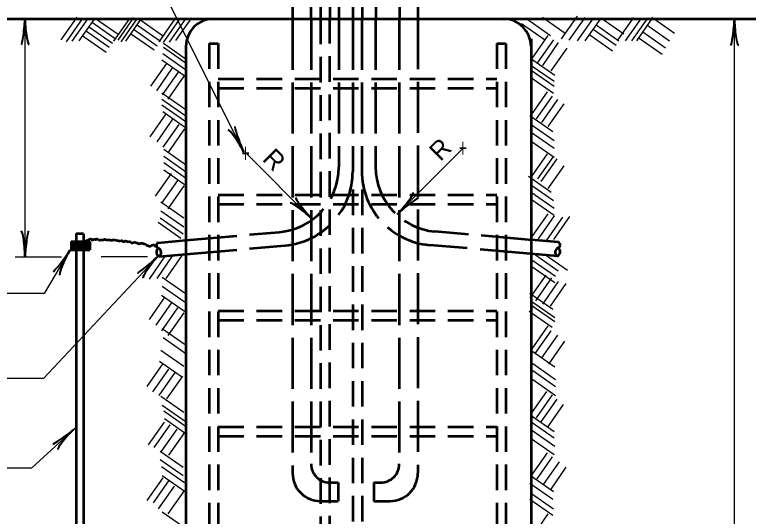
# Model space of a CAD drawing. Extents: x -711 to 145, y 25 to 569.
# Drawn here: x -347.5 to -252.6, y 105.2 to 170 of the extents above; entities that cross this region are included whole.
import ezdxf

# ---------------------------------------------------------------- set-up
doc = ezdxf.new("R2010")
doc.units = 0
doc.header["$LTSCALE"] = 1.1
doc.linetypes.add('LONG_DASHED', pattern=[7.5, 6, -1.5])
doc.linetypes.add('MEDIUM_DASHED', pattern=[4.5, 3, -1.5])
doc.layers.add('1', color=7, linetype='Continuous', lineweight=53)

msp = doc.modelspace()

# ---------------------------------------------------------------- linework, layer by layer
at = {"layer": '1', "lineweight": 25}
for p, q in [((-317.853, 152.275), (-331.719, 180.005)), ((-276.746, 166.889), (-274.682, 169.838)), ((-346.116, 138.621), (-346.116, 169.596)), ((-341.429, 166.753), (-339.365, 169.702)), ((-340.754, 166.528), (-338.689, 169.477)), ((-340.034, 166.573), (-337.969, 169.522)), ((-339.134, 166.618), (-337.069, 169.567)), ((-337.411, 169.003), (-334.462, 166.938)), ((-337.006, 169.543), (-334.057, 167.478)), ((-334.632, 166.573), (-332.568, 169.522)), ((-334.092, 166.708), (-332.028, 169.657)), ((-333.687, 166.528), (-331.622, 169.477)), ((-333.102, 166.573), (-331.037, 169.522)), ((-331.155, 169.318), (-328.206, 167.253)), ((-328.781, 166.528), (-326.716, 169.477)), ((-328.196, 166.438), (-326.131, 169.387)), ((-327.43, 166.483), (-325.366, 169.432)), ((-326.62, 166.663), (-324.555, 169.612)), ((-281.101, 169.408), (-278.152, 167.343)), ((-279.21, 169.678), (-276.261, 167.613)), ((-275.756, 166.709), (-273.691, 169.657)), ((-274.676, 166.619), (-272.611, 169.567)), ((-273.686, 166.619), (-271.621, 169.567)), ((-271.648, 169.588), (-268.699, 167.523)), ((-269.454, 166.709), (-267.39, 169.657)), ((-268.464, 166.619), (-266.399, 169.567)), ((-267.654, 166.619), (-265.589, 169.567)), ((-267.024, 166.619), (-264.959, 169.567)), ((-265.076, 169.678), (-262.127, 167.613)), ((-254.382, 81.637), (-254.382, 169.492)), ((-337.772, 168.418), (-334.822, 166.353)), ((-331.965, 168.058), (-329.016, 165.993)), ((-331.56, 168.643), (-328.611, 166.578)), ((-281.911, 168.868), (-278.962, 166.803)), ((-272.639, 168.148), (-269.69, 166.083)), ((-272.278, 168.688), (-269.329, 166.623)), ((-265.707, 168.688), (-262.758, 166.623)), ((-338.582, 167.247), (-335.633, 165.183)), ((-338.177, 167.877), (-335.228, 165.813)), ((-332.37, 167.517), (-329.421, 165.453)), ((-280.528, 164.368), (-278.463, 167.317)), ((-273.089, 167.427), (-270.14, 165.363)), ((-266.697, 166.977), (-263.748, 164.912)), ((-266.247, 167.787), (-263.298, 165.723)), ((-328.229, 166.347), (-325.28, 164.282)), ((-279.807, 163.828), (-277.743, 166.777)), ((-279.177, 163.468), (-277.112, 166.417)), ((-328.229, 165.807), (-325.28, 163.742)), ((-278.097, 162.748), (-276.032, 165.696)), ((-328.409, 164.186), (-325.46, 162.122)), ((-328.319, 164.997), (-325.37, 162.932)), ((-280.561, 164.276), (-277.612, 162.212)), ((-329.861, 160.767), (-327.796, 163.716)), ((-280.651, 163.466), (-277.702, 161.401)), ((-329.096, 160.182), (-327.031, 163.131)), ((-328.331, 159.641), (-326.266, 162.59)), ((-280.651, 162.836), (-277.702, 160.771)), ((-327.611, 159.101), (-325.546, 162.05)), ((-280.741, 161.936), (-277.792, 159.871)), ((-328.409, 159.91), (-325.46, 157.846)), ((-280.618, 157.076), (-278.553, 160.025)), ((-279.987, 156.536), (-277.923, 159.485)), ((-328.409, 159.1), (-325.46, 157.035)), ((-279.267, 156.085), (-277.202, 159.034)), ((-278.457, 155.545), (-276.392, 158.494)), ((-328.409, 158.38), (-325.46, 156.315)), ((-329.951, 154.24), (-327.886, 157.189)), ((-328.319, 157.48), (-325.37, 155.415)), ((-280.831, 156.984), (-277.882, 154.92)), ((-329.051, 153.565), (-326.986, 156.514)), ((-328.241, 152.889), (-326.176, 155.838)), ((-280.651, 155.814), (-277.702, 153.749)), ((-327.521, 152.304), (-325.456, 155.253)), ((-280.651, 154.824), (-277.702, 152.759)), ((-280.651, 153.654), (-277.702, 151.589)), ((-328.184, 152.618), (-325.235, 150.554)), ((-280.618, 149.064), (-278.553, 152.013)), ((-328.184, 151.718), (-325.235, 149.653)), ((-328.184, 150.908), (-325.235, 148.843)), ((-279.807, 148.793), (-277.743, 151.742)), ((-279.357, 148.433), (-277.292, 151.382)), ((-328.184, 149.963), (-325.235, 147.898)), ((-278.457, 147.533), (-276.392, 150.482)), ((-329.231, 146.543), (-327.166, 149.492)), ((-281.011, 149.152), (-278.062, 147.088)), ((-328.421, 145.643), (-326.356, 148.591)), ((-280.741, 148.072), (-277.792, 146.007)), ((-327.611, 144.922), (-325.546, 147.871)), ((-280.651, 147.082), (-277.702, 145.017)), ((-280.651, 146.181), (-277.702, 144.117)), ((-328.544, 145.821), (-325.595, 143.757)), ((-328.544, 144.651), (-325.595, 142.586)), ((-280.528, 141.322), (-278.463, 144.27)), ((-328.634, 143.751), (-325.685, 141.686)), ((-279.717, 141.051), (-277.653, 144)), ((-278.637, 140.871), (-276.572, 143.82)), ((-277.737, 140.961), (-275.672, 143.91)), ((-328.904, 143.211), (-325.955, 141.146)), ((-347.382, 138.703), (-341.382, 138.703)), ((-336.264, 138.748), (-330.264, 138.748)), ((-330.041, 135.83), (-327.976, 138.779)), ((-329.051, 135.92), (-326.986, 138.869)), ((-327.881, 135.92), (-325.816, 138.869)), ((-280.111, 138.979), (-277.161, 136.915)), ((-278.94, 139.07), (-275.991, 137.005)), ((-280.471, 138.259), (-277.522, 136.194)), ((-280.561, 137.449), (-277.612, 135.384)), ((-328.364, 136.099), (-325.415, 134.034)), ((-280.798, 133.399), (-278.733, 136.348)), ((-280.077, 133.039), (-278.013, 135.988)), ((-328.364, 134.928), (-325.415, 132.864)), ((-279.177, 132.589), (-277.112, 135.538)), ((-278.187, 132.319), (-276.122, 135.268)), ((-280.831, 134.028), (-277.882, 131.963)), ((-330.041, 130.608), (-327.976, 133.557)), ((-329.141, 129.888), (-327.076, 132.837)), ((-328.454, 133.758), (-325.505, 131.693)), ((-280.561, 132.948), (-277.612, 130.883)), ((-328.421, 129.168), (-326.356, 132.117)), ((-280.561, 132.408), (-277.612, 130.343)), ((-327.611, 128.538), (-325.546, 131.487)), ((-280.921, 131.687), (-277.972, 129.623)), ((-328.364, 129.437), (-325.415, 127.372)), ((-280.528, 126.828), (-278.463, 129.776)), ((-280.167, 126.197), (-278.103, 129.146)), ((-328.274, 128.267), (-325.325, 126.202)), ((-279.267, 125.657), (-277.202, 128.606)), ((-278.367, 124.847), (-276.302, 127.796)), ((-328.544, 126.646), (-325.595, 124.581)), ((-280.561, 126.556), (-277.612, 124.491)), ((-330.311, 121.966), (-328.247, 124.915)), ((-328.724, 125.206), (-325.775, 123.141)), ((-280.471, 124.936), (-277.522, 122.871)), ((-329.591, 121.246), (-327.526, 124.195)), ((-328.781, 120.796), (-326.716, 123.745)), ((-280.471, 124.035), (-277.522, 121.971)), ((-327.791, 120.346), (-325.726, 123.294)), ((-280.471, 122.865), (-277.522, 120.8)), ((-328.544, 120.705), (-325.595, 118.64)), ((-280.708, 118.365), (-278.643, 121.314)), ((-279.987, 117.915), (-277.923, 120.864)), ((-279.357, 117.375), (-277.292, 120.324)), ((-278.547, 116.655), (-276.482, 119.604)), ((-328.364, 119.534), (-325.415, 117.469)), ((-328.184, 118.814), (-325.235, 116.749)), ((-328.094, 117.824), (-325.145, 115.759)), ((-280.651, 118.184), (-277.702, 116.119)), ((-330.131, 114.404), (-328.067, 117.353)), ((-329.411, 114.044), (-327.346, 116.993)), ((-280.651, 117.374), (-277.702, 115.309)), ((-328.511, 113.504), (-326.446, 116.453)), ((-327.521, 113.053), (-325.456, 116.002)), ((-280.561, 116.293), (-277.612, 114.228)), ((-280.651, 115.213), (-277.702, 113.148)), ((-328.634, 113.592), (-325.685, 111.528)), ((-280.618, 110.443), (-278.553, 113.392)), ((-328.634, 112.512), (-325.685, 110.447)), ((-279.987, 109.903), (-277.923, 112.852)), ((-279.087, 109.273), (-277.022, 112.222)), ((-328.454, 111.612), (-325.505, 109.547)), ((-278.187, 108.552), (-276.122, 111.501)), ((-330.311, 107.202), (-328.247, 110.151)), ((-328.364, 110.442), (-325.415, 108.377)), ((-280.741, 110.442), (-277.792, 108.377)), ((-329.501, 106.932), (-327.436, 109.881)), ((-280.831, 109.451), (-277.882, 107.386)), ((-328.871, 106.122), (-326.806, 109.071)), ((-327.611, 105.491), (-325.546, 108.44)), ((-280.741, 108.191), (-277.792, 106.126)), ((-280.831, 107.381), (-277.882, 105.316)), ((-328.364, 105.76), (-325.415, 103.696)), ((-280.528, 102.521), (-278.463, 105.47))]:
    msp.add_line(p, q, dxfattribs=at)
at = {"layer": '1'}
for p, q in [((-305.538, 177.881), (-305.538, 169.481)), ((-303.738, 177.881), (-303.738, 169.481)), ((-302.538, 177.881), (-302.538, 169.481)), ((-300.738, 177.881), (-300.738, 169.481)), ((-311.546, 176.743), (-311.546, 169.492)), ((-309.146, 176.743), (-309.146, 169.492)), ((-297.708, 176.743), (-297.708, 169.543)), ((-295.308, 176.743), (-295.308, 169.543)), ((-307.923, 174.46), (-307.923, 169.492)), ((-306.723, 174.46), (-306.723, 169.492)), ((-359.367, 169.492), (-318.435, 169.492)), ((-321.725, 169.492), (-253.351, 169.492)), ((-263.611, 169.492), (-244.167, 169.492)), ((-280.687, 166.888), (-280.687, 81.935)), ((-339.509, 141.727), (-338.548, 141.727)), ((-339.509, 141.727), (-339.509, 140.802)), ((-338.548, 141.704), (-338.548, 141.315)), ((-338.548, 141.704), (-338.548, 140.802)), ((-340.139, 140.7), (-337.739, 140.7)), ((-340.139, 140.7), (-340.139, 139.62)), ((-340.094, 140.7), (-340.094, 139.62)), ((-340.083, 140.7), (-340.083, 139.62)), ((-340.06, 140.7), (-340.06, 139.62)), ((-340.038, 140.7), (-340.038, 139.62)), ((-340.004, 140.7), (-340.004, 139.62)), ((-339.947, 140.7), (-339.947, 139.62)), ((-339.891, 140.7), (-339.891, 139.62)), ((-339.835, 140.7), (-339.835, 139.62)), ((-339.812, 140.7), (-339.812, 139.62)), ((-339.767, 140.7), (-339.767, 139.62)), ((-339.756, 140.7), (-339.756, 139.62)), ((-339.722, 140.7), (-339.722, 139.62)), ((-339.689, 140.7), (-339.689, 139.62)), ((-339.689, 140.7), (-339.689, 139.62)), ((-339.677, 140.7), (-339.677, 139.62)), ((-339.666, 140.7), (-339.666, 139.62)), ((-339.632, 140.7), (-339.632, 139.62)), ((-339.61, 140.7), (-339.61, 139.62)), ((-339.599, 140.7), (-339.599, 139.62)), ((-339.565, 140.7), (-339.565, 139.62)), ((-339.565, 140.7), (-339.565, 139.62)), ((-339.554, 140.7), (-339.554, 139.62)), ((-339.52, 140.7), (-339.52, 139.62)), ((-339.509, 140.843), (-339.509, 138.047)), ((-339.486, 140.7), (-339.486, 139.62)), ((-339.486, 140.7), (-339.486, 139.62)), ((-339.441, 140.7), (-339.441, 139.62)), ((-339.441, 140.7), (-339.441, 139.62)), ((-339.419, 140.7), (-339.419, 139.62)), ((-339.418, 140.7), (-339.418, 140.267)), ((-339.374, 140.7), (-339.374, 139.62)), ((-339.374, 140.7), (-339.374, 139.62)), ((-339.34, 140.7), (-339.34, 139.62)), ((-339.317, 140.7), (-339.317, 139.62)), ((-339.295, 140.7), (-339.295, 139.62)), ((-339.261, 140.7), (-339.261, 139.62)), ((-339.239, 140.7), (-339.239, 139.62)), ((-339.205, 140.7), (-339.205, 139.62)), ((-339.171, 140.7), (-339.171, 139.62)), ((-339.16, 140.7), (-339.16, 139.62)), ((-339.149, 140.7), (-339.149, 139.62)), ((-339.126, 140.7), (-339.126, 139.62)), ((-339.104, 140.7), (-339.104, 139.62)), ((-339.092, 140.7), (-339.092, 139.62)), ((-339.07, 140.7), (-339.07, 139.62)), ((-339.059, 140.7), (-339.059, 139.62)), ((-339.047, 140.7), (-339.047, 139.62)), ((-339.025, 140.7), (-339.025, 139.62)), ((-339.025, 140.7), (-339.025, 139.62)), ((-339.025, 140.7), (-339.025, 139.62)), ((-338.991, 140.7), (-338.991, 139.62)), ((-338.991, 140.7), (-338.991, 139.62)), ((-338.957, 140.7), (-338.957, 139.62)), ((-338.957, 140.7), (-338.957, 139.62)), ((-338.946, 140.7), (-338.946, 139.62)), ((-338.924, 140.7), (-338.924, 139.62)), ((-338.879, 140.7), (-338.879, 139.62)), ((-338.867, 140.7), (-338.867, 139.62)), ((-338.867, 140.7), (-338.867, 139.62)), ((-338.845, 140.7), (-338.845, 139.62)), ((-338.811, 140.7), (-338.811, 139.62)), ((-338.8, 140.7), (-338.8, 139.62)), ((-338.789, 140.7), (-338.789, 139.62)), ((-338.777, 140.7), (-338.777, 139.62)), ((-338.766, 140.7), (-338.766, 139.62)), ((-338.732, 140.7), (-338.732, 139.62)), ((-338.71, 140.7), (-338.71, 139.62)), ((-338.699, 140.7), (-338.699, 139.62)), ((-338.676, 140.7), (-338.676, 139.62)), ((-338.642, 140.7), (-338.642, 139.62)), ((-338.62, 140.7), (-338.62, 139.62)), ((-338.62, 140.7), (-338.62, 139.62)), ((-338.608, 140.7), (-338.608, 139.62)), ((-338.597, 140.7), (-338.597, 139.62)), ((-338.575, 140.7), (-338.575, 139.62)), ((-338.575, 140.7), (-338.575, 139.62)), ((-338.564, 140.7), (-338.564, 139.62)), ((-338.548, 140.854), (-338.548, 138.091)), ((-338.541, 140.7), (-338.541, 139.62)), ((-338.541, 140.7), (-338.541, 139.62)), ((-338.53, 140.7), (-338.53, 139.62)), ((-338.507, 140.7), (-338.507, 139.62)), ((-338.485, 140.7), (-338.485, 139.62)), ((-338.474, 140.7), (-338.474, 139.62)), ((-338.459, 140.699), (-338.459, 140.267)), ((-338.451, 140.7), (-338.451, 139.62)), ((-338.44, 140.7), (-338.44, 139.62)), ((-338.429, 140.7), (-338.429, 139.62)), ((-338.395, 140.7), (-338.395, 139.62)), ((-338.361, 140.7), (-338.361, 139.62)), ((-338.35, 140.7), (-338.35, 139.62)), ((-338.339, 140.7), (-338.339, 139.62)), ((-338.316, 140.7), (-338.316, 139.62)), ((-338.305, 140.7), (-338.305, 139.62)), ((-338.293, 140.7), (-338.293, 139.62)), ((-338.26, 140.7), (-338.26, 139.62)), ((-338.215, 140.7), (-338.215, 139.62)), ((-338.204, 140.7), (-338.204, 139.62)), ((-338.204, 140.7), (-338.204, 139.62)), ((-338.204, 140.7), (-338.204, 139.62)), ((-338.192, 140.7), (-338.192, 139.62)), ((-338.159, 140.7), (-338.159, 139.62)), ((-338.159, 140.7), (-338.159, 139.62)), ((-338.147, 140.7), (-338.147, 139.62)), ((-338.136, 140.7), (-338.136, 139.62)), ((-338.114, 140.7), (-338.114, 139.62)), ((-338.102, 140.7), (-338.102, 139.62)), ((-338.091, 140.7), (-338.091, 139.62)), ((-338.069, 140.7), (-338.069, 139.62)), ((-338.046, 140.7), (-338.046, 139.62)), ((-338.035, 140.7), (-338.035, 139.62)), ((-338.024, 140.7), (-338.024, 139.62)), ((-338.024, 140.7), (-338.024, 139.62)), ((-337.99, 140.7), (-337.99, 139.62)), ((-337.967, 140.7), (-337.967, 139.62)), ((-337.967, 140.7), (-337.967, 139.62)), ((-337.956, 140.7), (-337.956, 139.62)), ((-337.956, 140.7), (-337.956, 139.62)), ((-337.922, 140.7), (-337.922, 139.62)), ((-337.911, 140.7), (-337.911, 139.62)), ((-337.911, 140.7), (-337.911, 139.62)), ((-337.889, 140.7), (-337.889, 139.62)), ((-337.889, 140.7), (-337.889, 139.62)), ((-337.889, 140.7), (-337.889, 139.62)), ((-337.877, 140.7), (-337.877, 139.62)), ((-337.877, 140.7), (-337.877, 139.62)), ((-337.832, 140.7), (-337.832, 139.62)), ((-337.821, 140.7), (-337.821, 139.62)), ((-337.81, 140.7), (-337.81, 139.62)), ((-337.787, 140.7), (-337.787, 139.62)), ((-337.787, 140.7), (-337.787, 139.62)), ((-337.776, 140.7), (-337.776, 139.62)), ((-337.776, 140.7), (-337.776, 139.62)), ((-337.742, 140.7), (-337.742, 139.62)), ((-337.739, 140.7), (-337.739, 139.62)), ((-328.929, 140.543), (-325.343, 140.857)), ((-277.118, 140.588), (-280.704, 140.902)), ((-340.139, 139.62), (-337.739, 139.62)), ((-328.772, 138.75), (-325.326, 139.051)), ((-277.275, 138.795), (-280.693, 139.094)), ((-339.509, 138.321), (-339.509, 69.075)), ((-338.548, 138.321), (-338.548, 69.075))]:
    msp.add_line(p, q, dxfattribs=at)
at = {"layer": '1', "linetype": 'LONG_DASHED'}
for p, q in [((-311.525, 169.498), (-311.525, 110.735)), ((-309.125, 169.498), (-309.125, 111.935)), ((-305.549, 169.498), (-305.549, 150.29)), ((-303.749, 169.498), (-303.749, 149.74)), ((-302.579, 169.498), (-302.579, 149.803)), ((-300.779, 169.498), (-300.779, 150.353)), ((-297.725, 169.498), (-297.725, 111.935)), ((-295.325, 169.588), (-295.325, 110.735)), ((-325.325, 140.863), (-313.217, 141.922)), ((-280.548, 140.886), (-293.111, 141.985)), ((-325.325, 139.056), (-312.513, 140.177)), ((-280.705, 139.093), (-293.816, 140.24)), ((-306.725, 109.535), (-305.639, 109.535)), ((-305.639, 109.535), (-305.639, 107.135)), ((-301.005, 109.535), (-300.125, 109.535)), ((-301.005, 109.535), (-301.005, 107.135)), ((-307.925, 107.135), (-305.639, 107.135)), ((-301.005, 107.135), (-298.925, 107.135))]:
    msp.add_line(p, q, dxfattribs=at)
at = {"layer": '1', "linetype": 'MEDIUM_DASHED'}
for p, q in [((-307.925, 169.498), (-307.925, 81.935)), ((-306.725, 169.588), (-306.725, 81.935)), ((-322.325, 166.298), (-322.325, 81.935)), ((-322.325, 166.298), (-321.125, 166.298)), ((-321.125, 166.298), (-321.125, 81.935)), ((-285.125, 166.298), (-285.125, 81.935)), ((-285.125, 166.298), (-283.925, 166.298)), ((-283.925, 166.298), (-283.925, 81.935)), ((-321.125, 161.735), (-285.125, 161.735)), ((-321.125, 160.535), (-285.125, 160.535)), ((-303.725, 147.399), (-303.725, 81.935)), ((-302.525, 147.399), (-302.525, 81.935)), ((-321.125, 146.735), (-285.125, 146.735)), ((-321.125, 145.535), (-285.125, 145.535)), ((-321.125, 131.735), (-285.125, 131.735)), ((-321.125, 130.535), (-285.125, 130.535)), ((-321.125, 116.735), (-285.125, 116.735)), ((-321.125, 115.535), (-285.125, 115.535))]:
    msp.add_line(p, q, dxfattribs=at)
at = {"layer": '1', "lineweight": 35}
for p, q in [((-309.01, 143.594), (-317.496, 152.079)), ((-297.999, 144.224), (-289.513, 152.71))]:
    msp.add_line(p, q, dxfattribs=at)
at = {"layer": '1'}
msp.add_lwpolyline([(-325.325, 165.892), (-325.325, 81.935), (-280.687, 81.935)], dxfattribs=at)
at = {"layer": '1', "lineweight": 25}
for points in [[(-340.311, 139.561), (-343.642, 133.98), (-349.05, 133.98)], [(-328.878, 138.841), (-343.732, 122.997), (-349.298, 122.997)], [(-339.681, 116.515), (-345.262, 111.384), (-369.712, 111.384)]]:
    msp.add_lwpolyline(points, dxfattribs=at)
at = {"layer": '1'}
for centre, radius, start, end in [((-321.725, 165.892), 3.6, 90, 180), ((-284.287, 165.892), 3.6, 0, 90), ((-328.497, 139.324), 0.636, 124.39884, 244.42408), ((-277.561, 139.369), 0.636, 295.57592, 55.60116)]:
    msp.add_arc(centre, radius, start, end, dxfattribs=at)
at = {"layer": '1', "lineweight": 25}
msp.add_arc((-321.725, 165.892), 3.6, 90, 180, dxfattribs=at)
at = {"layer": '1', "linetype": 'LONG_DASHED'}
for centre, radius, start, end in [((-313.949, 150.29), 8.4, 275.00041, 0), ((-292.379, 150.353), 8.4, 180, 264.9999), ((-313.349, 149.74), 9.6, 275.00013, 0), ((-292.979, 149.803), 9.6, 180, 264.9999), ((-306.725, 111.935), 2.4, 180, 270), ((-300.125, 111.935), 2.4, 270, 0), ((-307.925, 110.735), 3.6, 180, 270), ((-298.925, 110.735), 3.6, 270, 0)]:
    msp.add_arc(centre, radius, start, end, dxfattribs=at)
at = {"layer": '1', "lineweight": 40}
for centre, major_axis, ratio, start_param, end_param in [((-346.37, 168.251), (-0.211, -2.108), 0.07063, 6.282307, 8.559703), ((-345.785, 168.286), (-0.187, 2.143), 0.122415, 0.896353, 3.141593), ((-254.636, 168.148), (-0.211, -2.108), 0.07063, 6.282307, 8.559703), ((-254.051, 168.183), (-0.187, 2.143), 0.122415, 0.896353, 3.141593), ((-318.736, 153.298), (1.126, -1.833), 0.122415, 0.896353, 3.141593), ((-318.228, 153.591), (-0.754, 1.979), 0.07063, 6.282307, 8.559703), ((-309.782, 144.725), (1.341, -1.639), 0.07063, 3.140715, 5.41811), ((-297.307, 145.385), (-1.383, -1.648), 0.122415, 0.896353, 3.141593), ((-296.868, 144.996), (1.639, 1.341), 0.07063, 6.282307, 8.559703), ((-310.171, 144.286), (1.648, -1.383), 0.122415, 0.896353, 3.141593), ((-346.448, 139.931), (0.187, -2.143), 0.122415, 0.896353, 3.141593), ((-345.862, 139.966), (0.211, 2.108), 0.07063, 6.282307, 8.559703), ((-341.218, 138.537), (1.261, 1.702), 0.07063, 3.140715, 5.41811), ((-340.697, 138.267), (0.937, 1.936), 0.122415, 0.896353, 3.141593), ((-329.982, 138.034), (-1.595, -1.394), 0.07063, 6.282307, 8.559703), ((-329.531, 137.659), (1.329, 1.691), 0.122415, 0.896353, 3.141593), ((-340.842, 115.792), (-1.694, -1.271), 0.07063, 6.282307, 8.559703), ((-340.42, 115.385), (1.451, 1.588), 0.122415, 0.896353, 3.141593)]:
    msp.add_ellipse(centre, major_axis=major_axis, ratio=ratio, start_param=start_param, end_param=end_param, dxfattribs=at)
at = {"layer": '1'}
for centre, major_axis, ratio, start_param, end_param in [((-328.73, 140.228), (0.356, 0.225), 0.884789, 1.570796, 3.887311), ((-277.328, 140.273), (-0.356, 0.225), 0.884789, 2.395874, 4.712389), ((-329.131, 139.275), (0.58, -0.263), 0.984898, 5.752514, 7.853904), ((-276.928, 139.32), (0.58, 0.263), 0.984898, 1.570874, 3.672264)]:
    msp.add_ellipse(centre, major_axis=major_axis, ratio=ratio, start_param=start_param, end_param=end_param, dxfattribs=at)
msp.add_spline([(-338.374, 140.714), (-338.036, 140.872), (-337.564, 141.007), (-337.451, 140.917), (-337.091, 141.007), (-336.934, 140.939), (-336.799, 141.029), (-336.551, 140.872), (-336.394, 140.894), (-336.214, 140.894), (-336.033, 140.917), (-335.966, 140.894), (-335.808, 140.984), (-335.718, 140.939), (-335.493, 140.917), (-335.313, 140.894), (-335.111, 140.917), (-335.043, 140.849), (-334.863, 140.872), (-334.638, 140.917), (-334.346, 140.872), (-334.256, 140.827), (-334.053, 140.804), (-333.94, 140.759), (-333.648, 140.827), (-333.355, 140.669), (-333.22, 140.759), (-332.793, 140.669), (-332.545, 140.692), (-332.365, 140.534), (-332.072, 140.579), (-331.78, 140.579), (-331.51, 140.444), (-331.262, 140.422), (-331.15, 140.467), (-330.902, 140.467), (-330.767, 140.377), (-330.677, 140.377), (-330.385, 140.242), (-330.317, 140.129), (-330.317, 140.151), (-330.047, 140.084), (-329.867, 140.129), (-329.529, 140.264), (-329.394, 140.242), (-329.349, 140.151), (-329.304, 140.107), (-329.214, 140.107), (-329.012, 140.061)], degree=3, dxfattribs=at)

# ---------------------------------------------------------------- texts
for rotation, p in [(45, (-292.4, 150.95)), (315, (-315.551, 151.247))]:
    msp.add_text('R', height=2.4, rotation=rotation, dxfattribs=at).set_placement(p)
at = {"layer": '1', "width": 0.55}
for p in [(-318.112, 150.933), (-290, 151.597)]:
    msp.add_text('+', height=2.4, dxfattribs=at).set_placement(p)

doc.saveas('drawing.dxf')
